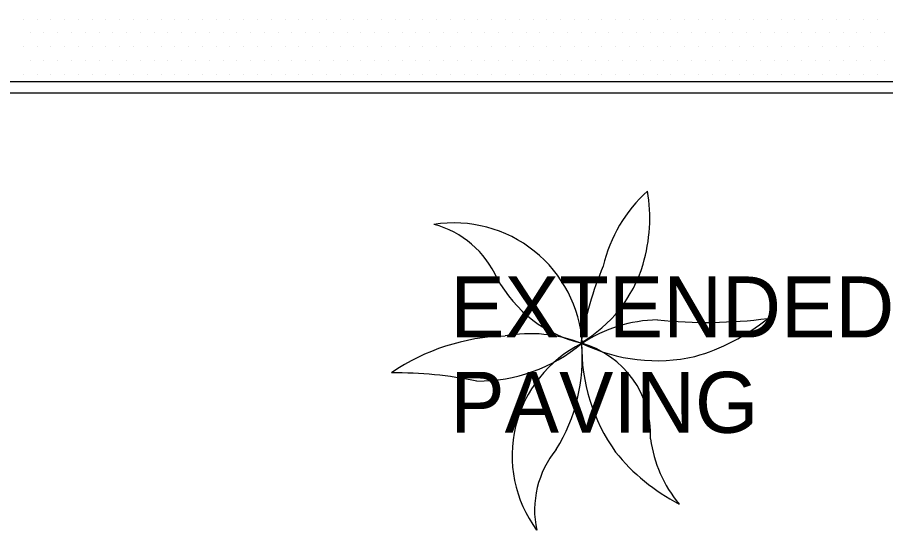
# Model space of a CAD drawing. Extents: x 6712138 to 6712574, y 1869536 to 1870160.
# Drawn here: x 6712356.5 to 6712395.89, y 1869702.41 to 1869725.74 of the extents above; entities that cross this region are included whole.
import ezdxf

# ---------------------------------------------------------------- set-up
doc = ezdxf.new("R2010")
doc.units = 0
for name, color, linetype in [('A-ANNO-TEXT', 7, 'Continuous'), ('A-FLOR-OTLN', 7, 'Continuous'), ('A-FLOR-PATT', 7, 'Continuous'), ('L-Palm', 7, 'Continuous'), ('L-PLNT-PALM', 7, 'Continuous')]:
    doc.layers.add(name, color=color, linetype=linetype)

# ---------------------------------------------------------------- blocks, each defined once
blk = doc.blocks.new('PALM_1')
at = {"layer": 'L-Palm'}
for centre, radius, start, end in [((0.3859, 0.0987), 0.3422, 132.6801, 166.8111), ((-0.2114, 0.2856), 0.371, 343.7522, 10.043), ((-0.29, -0.0226), 0.2968, 4.0873, 99.2555), ((-0.393, 0.0561), 0.2213, 24.2552, 75.5182), ((-0.1527, 0.2677), 0.3096, 300.1113, 343.9042), ((0.8252, -0.1374), 0.834, 157.8667, 170.5307), ((0.0708, 0.2901), 0.2986, 208.6354, 257.4748), ((0.1868, -0.2705), 0.3242, 91.3382, 124.0385), ((0.2849, 1.1558), 1.1072, 264.5234, 277.6792), ((0.1358, 0.4172), 0.4657, 286.1702, 309.6262), ((-0.1563, -0.4706), 0.4851, 91.8686, 124.7845), ((-0.1117, -0.3019), 0.3219, 68.8397, 100.8216), ((-0.2364, 0.2825), 0.3726, 270.0402, 310.2895), ((0.1346, -0.2597), 0.2886, 116.7925, 216.8342), ((-0.3946, -0.0377), 0.4007, 328.6183, 5.0923), ((0.4257, -0.0051), 0.4212, 179.4834, 215.787), ((-0.0535, -0.2115), 0.2181, 357.6134, 74.5522), ((0.1756, 0.3541), 0.3946, 244.4343, 283.1777), ((-0.4218, -1.0386), 0.9665, 78.9259, 90.6662), ((0.4639, -0.1765), 0.3027, 188.3856, 219.8245), ((0.1198, -0.3852), 0.2213, 141.1268, 192.3899), ((0.4441, 0.0439), 0.4657, 219.354, 242.8101)]:
    blk.add_arc(centre, radius, start, end, dxfattribs=at)

msp = doc.modelspace()

# ---------------------------------------------------------------- linework, layer by layer
at = {"layer": 'A-FLOR-OTLN'}
for points in [[(6712251.183, 1869839.781), (6712251.183, 1869722.323), (6712419.14, 1869722.323), (6712419.14, 1869718.864), (6712468.641, 1869718.864), (6712468.641, 1869839.781)], [(6712251.683, 1869839.281), (6712251.683, 1869722.823), (6712419.64, 1869722.823), (6712419.64, 1869719.364), (6712468.141, 1869719.364), (6712468.141, 1869839.281)]]:
    msp.add_lwpolyline(points, close=True, dxfattribs=at)
at = {"layer": 'A-FLOR-PATT'}
for p, q in [((6712356.774, 1869725.657), (6712356.774, 1869725.657)), ((6712357.399, 1869725.657), (6712357.399, 1869725.657)), ((6712358.024, 1869725.657), (6712358.024, 1869725.657)), ((6712358.649, 1869725.657), (6712358.649, 1869725.657)), ((6712359.274, 1869725.657), (6712359.274, 1869725.657)), ((6712359.899, 1869725.657), (6712359.899, 1869725.657)), ((6712360.524, 1869725.657), (6712360.524, 1869725.657)), ((6712361.149, 1869725.657), (6712361.149, 1869725.657)), ((6712361.774, 1869725.657), (6712361.774, 1869725.657)), ((6712362.399, 1869725.657), (6712362.399, 1869725.657)), ((6712363.024, 1869725.657), (6712363.024, 1869725.657)), ((6712363.649, 1869725.657), (6712363.649, 1869725.657)), ((6712364.274, 1869725.657), (6712364.274, 1869725.657)), ((6712364.899, 1869725.657), (6712364.899, 1869725.657)), ((6712365.524, 1869725.657), (6712365.524, 1869725.657)), ((6712366.149, 1869725.657), (6712366.149, 1869725.657)), ((6712366.774, 1869725.657), (6712366.774, 1869725.657)), ((6712367.399, 1869725.657), (6712367.399, 1869725.657)), ((6712368.024, 1869725.657), (6712368.024, 1869725.657)), ((6712368.649, 1869725.657), (6712368.649, 1869725.657)), ((6712369.274, 1869725.657), (6712369.274, 1869725.657)), ((6712369.899, 1869725.657), (6712369.899, 1869725.657)), ((6712370.524, 1869725.657), (6712370.524, 1869725.657)), ((6712371.149, 1869725.657), (6712371.149, 1869725.657)), ((6712371.774, 1869725.657), (6712371.774, 1869725.657)), ((6712372.399, 1869725.657), (6712372.399, 1869725.657)), ((6712373.024, 1869725.657), (6712373.024, 1869725.657)), ((6712373.649, 1869725.657), (6712373.649, 1869725.657)), ((6712374.274, 1869725.657), (6712374.274, 1869725.657)), ((6712374.899, 1869725.657), (6712374.899, 1869725.657)), ((6712375.524, 1869725.657), (6712375.524, 1869725.657)), ((6712376.149, 1869725.657), (6712376.149, 1869725.657)), ((6712376.774, 1869725.657), (6712376.774, 1869725.657)), ((6712377.399, 1869725.657), (6712377.399, 1869725.657)), ((6712378.024, 1869725.657), (6712378.024, 1869725.657)), ((6712378.649, 1869725.657), (6712378.649, 1869725.657)), ((6712379.274, 1869725.657), (6712379.274, 1869725.657)), ((6712379.899, 1869725.657), (6712379.899, 1869725.657)), ((6712380.524, 1869725.657), (6712380.524, 1869725.657)), ((6712381.149, 1869725.657), (6712381.149, 1869725.657)), ((6712381.774, 1869725.657), (6712381.774, 1869725.657)), ((6712382.399, 1869725.657), (6712382.399, 1869725.657)), ((6712383.024, 1869725.657), (6712383.024, 1869725.657)), ((6712383.649, 1869725.657), (6712383.649, 1869725.657)), ((6712384.274, 1869725.657), (6712384.274, 1869725.657)), ((6712384.899, 1869725.657), (6712384.899, 1869725.657)), ((6712385.524, 1869725.657), (6712385.524, 1869725.657)), ((6712386.149, 1869725.657), (6712386.149, 1869725.657)), ((6712386.774, 1869725.657), (6712386.774, 1869725.657)), ((6712387.399, 1869725.657), (6712387.399, 1869725.657)), ((6712388.024, 1869725.657), (6712388.024, 1869725.657)), ((6712388.649, 1869725.657), (6712388.649, 1869725.657)), ((6712389.274, 1869725.657), (6712389.274, 1869725.657)), ((6712389.899, 1869725.657), (6712389.899, 1869725.657)), ((6712390.524, 1869725.657), (6712390.524, 1869725.657)), ((6712391.149, 1869725.657), (6712391.149, 1869725.657)), ((6712391.774, 1869725.657), (6712391.774, 1869725.657)), ((6712392.399, 1869725.657), (6712392.399, 1869725.657)), ((6712393.024, 1869725.657), (6712393.024, 1869725.657)), ((6712393.649, 1869725.657), (6712393.649, 1869725.657)), ((6712394.274, 1869725.657), (6712394.274, 1869725.657)), ((6712394.899, 1869725.657), (6712394.899, 1869725.657)), ((6712395.524, 1869725.657), (6712395.524, 1869725.657)), ((6712357.087, 1869725.032), (6712357.087, 1869725.032)), ((6712357.712, 1869725.032), (6712357.712, 1869725.032)), ((6712358.337, 1869725.032), (6712358.337, 1869725.032)), ((6712358.962, 1869725.032), (6712358.962, 1869725.032)), ((6712359.587, 1869725.032), (6712359.587, 1869725.032)), ((6712360.212, 1869725.032), (6712360.212, 1869725.032)), ((6712360.837, 1869725.032), (6712360.837, 1869725.032)), ((6712361.462, 1869725.032), (6712361.462, 1869725.032)), ((6712362.087, 1869725.032), (6712362.087, 1869725.032)), ((6712362.712, 1869725.032), (6712362.712, 1869725.032)), ((6712363.337, 1869725.032), (6712363.337, 1869725.032)), ((6712363.962, 1869725.032), (6712363.962, 1869725.032)), ((6712364.587, 1869725.032), (6712364.587, 1869725.032)), ((6712365.212, 1869725.032), (6712365.212, 1869725.032)), ((6712365.837, 1869725.032), (6712365.837, 1869725.032)), ((6712366.462, 1869725.032), (6712366.462, 1869725.032)), ((6712367.087, 1869725.032), (6712367.087, 1869725.032)), ((6712367.712, 1869725.032), (6712367.712, 1869725.032)), ((6712368.337, 1869725.032), (6712368.337, 1869725.032)), ((6712368.962, 1869725.032), (6712368.962, 1869725.032)), ((6712369.587, 1869725.032), (6712369.587, 1869725.032)), ((6712370.212, 1869725.032), (6712370.212, 1869725.032)), ((6712370.837, 1869725.032), (6712370.837, 1869725.032)), ((6712371.462, 1869725.032), (6712371.462, 1869725.032)), ((6712372.087, 1869725.032), (6712372.087, 1869725.032)), ((6712372.712, 1869725.032), (6712372.712, 1869725.032)), ((6712373.337, 1869725.032), (6712373.337, 1869725.032)), ((6712373.962, 1869725.032), (6712373.962, 1869725.032)), ((6712374.587, 1869725.032), (6712374.587, 1869725.032)), ((6712375.212, 1869725.032), (6712375.212, 1869725.032)), ((6712375.837, 1869725.032), (6712375.837, 1869725.032)), ((6712376.462, 1869725.032), (6712376.462, 1869725.032)), ((6712377.087, 1869725.032), (6712377.087, 1869725.032)), ((6712377.712, 1869725.032), (6712377.712, 1869725.032)), ((6712378.337, 1869725.032), (6712378.337, 1869725.032)), ((6712378.962, 1869725.032), (6712378.962, 1869725.032)), ((6712379.587, 1869725.032), (6712379.587, 1869725.032)), ((6712380.212, 1869725.032), (6712380.212, 1869725.032)), ((6712380.837, 1869725.032), (6712380.837, 1869725.032)), ((6712381.462, 1869725.032), (6712381.462, 1869725.032)), ((6712382.087, 1869725.032), (6712382.087, 1869725.032)), ((6712382.712, 1869725.032), (6712382.712, 1869725.032)), ((6712383.337, 1869725.032), (6712383.337, 1869725.032)), ((6712383.962, 1869725.032), (6712383.962, 1869725.032)), ((6712384.587, 1869725.032), (6712384.587, 1869725.032)), ((6712385.212, 1869725.032), (6712385.212, 1869725.032)), ((6712385.837, 1869725.032), (6712385.837, 1869725.032)), ((6712386.462, 1869725.032), (6712386.462, 1869725.032)), ((6712387.087, 1869725.032), (6712387.087, 1869725.032)), ((6712387.712, 1869725.032), (6712387.712, 1869725.032)), ((6712388.337, 1869725.032), (6712388.337, 1869725.032)), ((6712388.962, 1869725.032), (6712388.962, 1869725.032)), ((6712389.587, 1869725.032), (6712389.587, 1869725.032)), ((6712390.212, 1869725.032), (6712390.212, 1869725.032)), ((6712390.837, 1869725.032), (6712390.837, 1869725.032)), ((6712391.462, 1869725.032), (6712391.462, 1869725.032)), ((6712392.087, 1869725.032), (6712392.087, 1869725.032)), ((6712392.712, 1869725.032), (6712392.712, 1869725.032)), ((6712393.337, 1869725.032), (6712393.337, 1869725.032)), ((6712393.962, 1869725.032), (6712393.962, 1869725.032)), ((6712394.587, 1869725.032), (6712394.587, 1869725.032)), ((6712395.212, 1869725.032), (6712395.212, 1869725.032)), ((6712395.837, 1869725.032), (6712395.837, 1869725.032)), ((6712356.774, 1869724.407), (6712356.774, 1869724.407)), ((6712357.399, 1869724.407), (6712357.399, 1869724.407)), ((6712358.024, 1869724.407), (6712358.024, 1869724.407)), ((6712358.649, 1869724.407), (6712358.649, 1869724.407)), ((6712359.274, 1869724.407), (6712359.274, 1869724.407)), ((6712359.899, 1869724.407), (6712359.899, 1869724.407)), ((6712360.524, 1869724.407), (6712360.524, 1869724.407)), ((6712361.149, 1869724.407), (6712361.149, 1869724.407)), ((6712361.774, 1869724.407), (6712361.774, 1869724.407)), ((6712362.399, 1869724.407), (6712362.399, 1869724.407)), ((6712363.024, 1869724.407), (6712363.024, 1869724.407)), ((6712363.649, 1869724.407), (6712363.649, 1869724.407)), ((6712364.274, 1869724.407), (6712364.274, 1869724.407)), ((6712364.899, 1869724.407), (6712364.899, 1869724.407)), ((6712365.524, 1869724.407), (6712365.524, 1869724.407)), ((6712366.149, 1869724.407), (6712366.149, 1869724.407)), ((6712366.774, 1869724.407), (6712366.774, 1869724.407)), ((6712367.399, 1869724.407), (6712367.399, 1869724.407)), ((6712368.024, 1869724.407), (6712368.024, 1869724.407)), ((6712368.649, 1869724.407), (6712368.649, 1869724.407)), ((6712369.274, 1869724.407), (6712369.274, 1869724.407)), ((6712369.899, 1869724.407), (6712369.899, 1869724.407)), ((6712370.524, 1869724.407), (6712370.524, 1869724.407)), ((6712371.149, 1869724.407), (6712371.149, 1869724.407)), ((6712371.774, 1869724.407), (6712371.774, 1869724.407)), ((6712372.399, 1869724.407), (6712372.399, 1869724.407)), ((6712373.024, 1869724.407), (6712373.024, 1869724.407)), ((6712373.649, 1869724.407), (6712373.649, 1869724.407)), ((6712374.274, 1869724.407), (6712374.274, 1869724.407)), ((6712374.899, 1869724.407), (6712374.899, 1869724.407)), ((6712375.524, 1869724.407), (6712375.524, 1869724.407)), ((6712376.149, 1869724.407), (6712376.149, 1869724.407)), ((6712376.774, 1869724.407), (6712376.774, 1869724.407)), ((6712377.399, 1869724.407), (6712377.399, 1869724.407)), ((6712378.024, 1869724.407), (6712378.024, 1869724.407)), ((6712378.649, 1869724.407), (6712378.649, 1869724.407)), ((6712379.274, 1869724.407), (6712379.274, 1869724.407)), ((6712379.899, 1869724.407), (6712379.899, 1869724.407)), ((6712380.524, 1869724.407), (6712380.524, 1869724.407)), ((6712381.149, 1869724.407), (6712381.149, 1869724.407)), ((6712381.774, 1869724.407), (6712381.774, 1869724.407)), ((6712382.399, 1869724.407), (6712382.399, 1869724.407)), ((6712383.024, 1869724.407), (6712383.024, 1869724.407)), ((6712383.649, 1869724.407), (6712383.649, 1869724.407)), ((6712384.274, 1869724.407), (6712384.274, 1869724.407)), ((6712384.899, 1869724.407), (6712384.899, 1869724.407)), ((6712385.524, 1869724.407), (6712385.524, 1869724.407)), ((6712386.149, 1869724.407), (6712386.149, 1869724.407)), ((6712386.774, 1869724.407), (6712386.774, 1869724.407)), ((6712387.399, 1869724.407), (6712387.399, 1869724.407)), ((6712388.024, 1869724.407), (6712388.024, 1869724.407)), ((6712388.649, 1869724.407), (6712388.649, 1869724.407)), ((6712389.274, 1869724.407), (6712389.274, 1869724.407)), ((6712389.899, 1869724.407), (6712389.899, 1869724.407)), ((6712390.524, 1869724.407), (6712390.524, 1869724.407)), ((6712391.149, 1869724.407), (6712391.149, 1869724.407)), ((6712391.774, 1869724.407), (6712391.774, 1869724.407)), ((6712392.399, 1869724.407), (6712392.399, 1869724.407)), ((6712393.024, 1869724.407), (6712393.024, 1869724.407)), ((6712393.649, 1869724.407), (6712393.649, 1869724.407)), ((6712394.274, 1869724.407), (6712394.274, 1869724.407)), ((6712394.899, 1869724.407), (6712394.899, 1869724.407)), ((6712395.524, 1869724.407), (6712395.524, 1869724.407)), ((6712357.087, 1869723.782), (6712357.087, 1869723.782)), ((6712357.712, 1869723.782), (6712357.712, 1869723.782)), ((6712358.337, 1869723.782), (6712358.337, 1869723.782)), ((6712358.962, 1869723.782), (6712358.962, 1869723.782)), ((6712359.587, 1869723.782), (6712359.587, 1869723.782)), ((6712360.212, 1869723.782), (6712360.212, 1869723.782)), ((6712360.837, 1869723.782), (6712360.837, 1869723.782)), ((6712361.462, 1869723.782), (6712361.462, 1869723.782)), ((6712362.087, 1869723.782), (6712362.087, 1869723.782)), ((6712362.712, 1869723.782), (6712362.712, 1869723.782)), ((6712363.337, 1869723.782), (6712363.337, 1869723.782)), ((6712363.962, 1869723.782), (6712363.962, 1869723.782)), ((6712364.587, 1869723.782), (6712364.587, 1869723.782)), ((6712365.212, 1869723.782), (6712365.212, 1869723.782)), ((6712365.837, 1869723.782), (6712365.837, 1869723.782)), ((6712366.462, 1869723.782), (6712366.462, 1869723.782)), ((6712367.087, 1869723.782), (6712367.087, 1869723.782)), ((6712367.712, 1869723.782), (6712367.712, 1869723.782)), ((6712368.337, 1869723.782), (6712368.337, 1869723.782)), ((6712368.962, 1869723.782), (6712368.962, 1869723.782)), ((6712369.587, 1869723.782), (6712369.587, 1869723.782)), ((6712370.212, 1869723.782), (6712370.212, 1869723.782)), ((6712370.837, 1869723.782), (6712370.837, 1869723.782)), ((6712371.462, 1869723.782), (6712371.462, 1869723.782)), ((6712372.087, 1869723.782), (6712372.087, 1869723.782)), ((6712372.712, 1869723.782), (6712372.712, 1869723.782)), ((6712373.337, 1869723.782), (6712373.337, 1869723.782)), ((6712373.962, 1869723.782), (6712373.962, 1869723.782)), ((6712374.587, 1869723.782), (6712374.587, 1869723.782)), ((6712375.212, 1869723.782), (6712375.212, 1869723.782)), ((6712375.837, 1869723.782), (6712375.837, 1869723.782)), ((6712376.462, 1869723.782), (6712376.462, 1869723.782)), ((6712377.087, 1869723.782), (6712377.087, 1869723.782)), ((6712377.712, 1869723.782), (6712377.712, 1869723.782)), ((6712378.337, 1869723.782), (6712378.337, 1869723.782)), ((6712378.962, 1869723.782), (6712378.962, 1869723.782)), ((6712379.587, 1869723.782), (6712379.587, 1869723.782)), ((6712380.212, 1869723.782), (6712380.212, 1869723.782)), ((6712380.837, 1869723.782), (6712380.837, 1869723.782)), ((6712381.462, 1869723.782), (6712381.462, 1869723.782)), ((6712382.087, 1869723.782), (6712382.087, 1869723.782)), ((6712382.712, 1869723.782), (6712382.712, 1869723.782)), ((6712383.337, 1869723.782), (6712383.337, 1869723.782)), ((6712383.962, 1869723.782), (6712383.962, 1869723.782)), ((6712384.587, 1869723.782), (6712384.587, 1869723.782)), ((6712385.212, 1869723.782), (6712385.212, 1869723.782)), ((6712385.837, 1869723.782), (6712385.837, 1869723.782)), ((6712386.462, 1869723.782), (6712386.462, 1869723.782)), ((6712387.087, 1869723.782), (6712387.087, 1869723.782)), ((6712387.712, 1869723.782), (6712387.712, 1869723.782)), ((6712388.337, 1869723.782), (6712388.337, 1869723.782)), ((6712388.962, 1869723.782), (6712388.962, 1869723.782)), ((6712389.587, 1869723.782), (6712389.587, 1869723.782)), ((6712390.212, 1869723.782), (6712390.212, 1869723.782)), ((6712390.837, 1869723.782), (6712390.837, 1869723.782)), ((6712391.462, 1869723.782), (6712391.462, 1869723.782)), ((6712392.087, 1869723.782), (6712392.087, 1869723.782)), ((6712392.712, 1869723.782), (6712392.712, 1869723.782)), ((6712393.337, 1869723.782), (6712393.337, 1869723.782)), ((6712393.962, 1869723.782), (6712393.962, 1869723.782)), ((6712394.587, 1869723.782), (6712394.587, 1869723.782)), ((6712395.212, 1869723.782), (6712395.212, 1869723.782)), ((6712395.837, 1869723.782), (6712395.837, 1869723.782)), ((6712356.774, 1869723.157), (6712356.774, 1869723.157)), ((6712357.399, 1869723.157), (6712357.399, 1869723.157)), ((6712358.024, 1869723.157), (6712358.024, 1869723.157)), ((6712358.649, 1869723.157), (6712358.649, 1869723.157)), ((6712359.274, 1869723.157), (6712359.274, 1869723.157)), ((6712359.899, 1869723.157), (6712359.899, 1869723.157)), ((6712360.524, 1869723.157), (6712360.524, 1869723.157)), ((6712361.149, 1869723.157), (6712361.149, 1869723.157)), ((6712361.774, 1869723.157), (6712361.774, 1869723.157)), ((6712362.399, 1869723.157), (6712362.399, 1869723.157)), ((6712363.024, 1869723.157), (6712363.024, 1869723.157)), ((6712363.649, 1869723.157), (6712363.649, 1869723.157)), ((6712364.274, 1869723.157), (6712364.274, 1869723.157)), ((6712364.899, 1869723.157), (6712364.899, 1869723.157)), ((6712365.524, 1869723.157), (6712365.524, 1869723.157)), ((6712366.149, 1869723.157), (6712366.149, 1869723.157)), ((6712366.774, 1869723.157), (6712366.774, 1869723.157)), ((6712367.399, 1869723.157), (6712367.399, 1869723.157)), ((6712368.024, 1869723.157), (6712368.024, 1869723.157)), ((6712368.649, 1869723.157), (6712368.649, 1869723.157)), ((6712369.274, 1869723.157), (6712369.274, 1869723.157)), ((6712369.899, 1869723.157), (6712369.899, 1869723.157)), ((6712370.524, 1869723.157), (6712370.524, 1869723.157)), ((6712371.149, 1869723.157), (6712371.149, 1869723.157)), ((6712371.774, 1869723.157), (6712371.774, 1869723.157)), ((6712372.399, 1869723.157), (6712372.399, 1869723.157)), ((6712373.024, 1869723.157), (6712373.024, 1869723.157)), ((6712373.649, 1869723.157), (6712373.649, 1869723.157)), ((6712374.274, 1869723.157), (6712374.274, 1869723.157)), ((6712374.899, 1869723.157), (6712374.899, 1869723.157)), ((6712375.524, 1869723.157), (6712375.524, 1869723.157)), ((6712376.149, 1869723.157), (6712376.149, 1869723.157)), ((6712376.774, 1869723.157), (6712376.774, 1869723.157)), ((6712377.399, 1869723.157), (6712377.399, 1869723.157)), ((6712378.024, 1869723.157), (6712378.024, 1869723.157)), ((6712378.649, 1869723.157), (6712378.649, 1869723.157)), ((6712379.274, 1869723.157), (6712379.274, 1869723.157)), ((6712379.899, 1869723.157), (6712379.899, 1869723.157)), ((6712380.524, 1869723.157), (6712380.524, 1869723.157)), ((6712381.149, 1869723.157), (6712381.149, 1869723.157)), ((6712381.774, 1869723.157), (6712381.774, 1869723.157)), ((6712382.399, 1869723.157), (6712382.399, 1869723.157)), ((6712383.024, 1869723.157), (6712383.024, 1869723.157)), ((6712383.649, 1869723.157), (6712383.649, 1869723.157)), ((6712384.274, 1869723.157), (6712384.274, 1869723.157)), ((6712384.899, 1869723.157), (6712384.899, 1869723.157)), ((6712385.524, 1869723.157), (6712385.524, 1869723.157)), ((6712386.149, 1869723.157), (6712386.149, 1869723.157)), ((6712386.774, 1869723.157), (6712386.774, 1869723.157)), ((6712387.399, 1869723.157), (6712387.399, 1869723.157)), ((6712388.024, 1869723.157), (6712388.024, 1869723.157)), ((6712388.649, 1869723.157), (6712388.649, 1869723.157)), ((6712389.274, 1869723.157), (6712389.274, 1869723.157)), ((6712389.899, 1869723.157), (6712389.899, 1869723.157)), ((6712390.524, 1869723.157), (6712390.524, 1869723.157)), ((6712391.149, 1869723.157), (6712391.149, 1869723.157)), ((6712391.774, 1869723.157), (6712391.774, 1869723.157)), ((6712392.399, 1869723.157), (6712392.399, 1869723.157)), ((6712393.024, 1869723.157), (6712393.024, 1869723.157)), ((6712393.649, 1869723.157), (6712393.649, 1869723.157)), ((6712394.274, 1869723.157), (6712394.274, 1869723.157)), ((6712394.899, 1869723.157), (6712394.899, 1869723.157)), ((6712395.524, 1869723.157), (6712395.524, 1869723.157))]:
    msp.add_line(p, q, dxfattribs=at)

# ---------------------------------------------------------------- block references
at = {"layer": 'L-PLNT-PALM', "xscale": 19.685039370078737, "yscale": 19.68503937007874, "rotation": -0.36974722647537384}
msp.add_blockref('PALM_1', (6712382.013, 1869710.982), dxfattribs=at)

# ---------------------------------------------------------------- texts
at = {"layer": 'A-ANNO-TEXT'}
for s, height, p in [('EXTENDED PLAZA ', 2.76619, (6712376.141, 1869711.22)), ('EXTENDED PLAZA ', 2.76619, (6712376.141, 1869711.22)), ('PAVING', 2.7662, (6712376.141, 1869706.893)), ('PAVING', 2.7662, (6712376.141, 1869706.893))]:
    msp.add_text(s, height=height, dxfattribs=at).set_placement(p)

doc.saveas('drawing.dxf')
